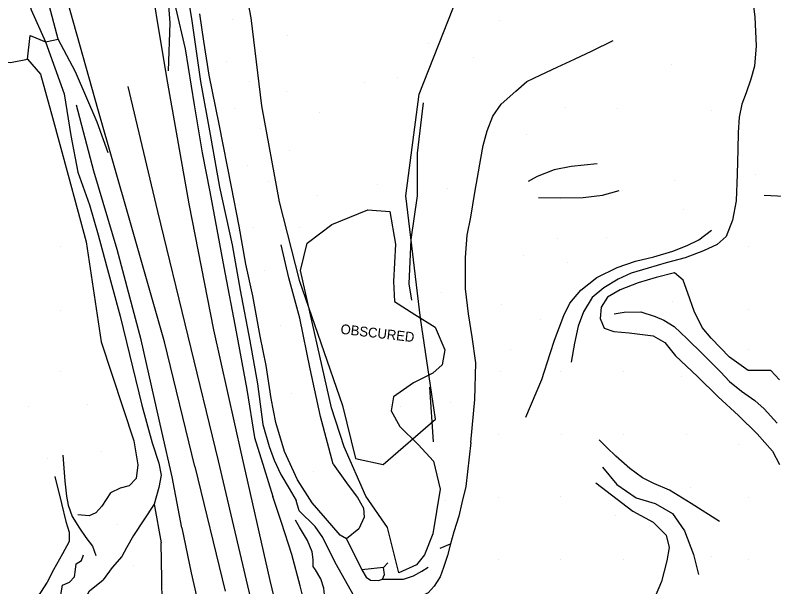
# Model space of a CAD drawing. Extents: x 524772 to 528246, y 273285 to 283088.
# Drawn here: x 526883.1 to 527001.3, y 277096 to 277185.1 of the extents above; entities that cross this region are included whole.
import ezdxf

# ---------------------------------------------------------------- set-up
doc = ezdxf.new("R2010")
doc.units = 0
for name, color, linetype in [('Exist DTM Crownline', 7, 'Continuous'), ('Exist Roads EOP', 7, 'Continuous'), ('Old_Level_12', 7, 'Continuous'), ('PH Exist DTM Breakline', 7, 'Continuous'), ('PH Exist DTM Obscure Area', 7, 'Continuous'), ('PH Exist DTM Obscure Area Text', 7, 'Continuous'), ('PH Exist DTM Point', 7, 'Continuous')]:
    doc.layers.add(name, color=color, linetype=linetype)

msp = doc.modelspace()

# ---------------------------------------------------------------- linework, layer by layer
at = {"layer": 'Exist DTM Crownline'}
for points in [[(526914.79, 277115.69), (526910.06, 277135.12), (526905.32, 277154.55), (526900.69, 277174)], [(526919.33, 277096.21), (526914.79, 277115.69)], [(526947.06, 276979.45), (526942.42, 276998.91), (526937.88, 277018.39), (526933.24, 277037.84), (526928.61, 277057.3), (526923.97, 277076.75), (526919.33, 277096.21)]]:
    msp.add_lwpolyline(points, dxfattribs=at)
at = {"layer": 'Exist Roads EOP'}
for points in [[(526900.85, 277153.48), (526896.06, 277170.16), (526889.3, 277194.22), (526884.63, 277212.43), (526879.92, 277231.7), (526876.48, 277244.99), (526874.79, 277251.63), (526873.56, 277255.42), (526872.21, 277259), (526870.14, 277262.76), (526866.56, 277267.72), (526863.21, 277269.57), (526861.12, 277271.45), (526858.18, 277272.32), (526855.9, 277272.51), (526842.82, 277270.02)], [(526918.39, 277116.54), (526914.05, 277136.07), (526910.19, 277155.71), (526906.72, 277175.44), (526903.44, 277195.22), (526899.97, 277214.95)], [(526911.1, 277114.8), (526906.36, 277134.24), (526900.85, 277153.48)], [(526922.83, 277097.04), (526918.39, 277116.54)], [(526911.1, 277114.8), (526915.83, 277095.37)], [(526950.66, 276980.31), (526946.02, 276999.77), (526941.38, 277019.22), (526936.75, 277038.68), (526932.11, 277058.13), (526927.47, 277077.59), (526922.83, 277097.04)]]:
    msp.add_lwpolyline(points, dxfattribs=at)
at = {"layer": 'Old_Level_12'}
msp.add_lwpolyline([(526918, 277194.33), (526919.81, 277184.72), (526921.45, 277171.02), (526924.24, 277156.03), (526927.35, 277143.85), (526934.11, 277124.3), (526936.12, 277116.04), (526940.41, 277115.08), (526948.6, 277122.14), (526946.23, 277137.9), (526943.97, 277156.98), (526946.05, 277172.83), (526953.62, 277192.1)], dxfattribs=at)
at = {"layer": 'PH Exist DTM Breakline'}
for points in [[(526897.58, 277163.67), (526895.87, 277168.46), (526892.48, 277176.3), (526889.8, 277181.4), (526886.36, 277194.4), (526883.53, 277204.48), (526881.07, 277212.38), (526878.38, 277221.11), (526875.84, 277229.51), (526876.25, 277230.28), (526876.28, 277232.3), (526876.33, 277233.77), (526876.07, 277235.6), (526875.05, 277239.42), (526873.73, 277244.72), (526872.03, 277251.84), (526869.74, 277261.27), (526868.77, 277263.43), (526868.32, 277264.16), (526867.85, 277264.89), (526867.37, 277265.6), (526866.86, 277266.3), (526866.33, 277266.98), (526865.86, 277267.56)], [(526906.97, 277176.46), (526907.26, 277183.92), (526906.54, 277192.83), (526905.68, 277202.3), (526904.42, 277210.29), (526901.93, 277222), (526900, 277232.75), (526897.48, 277243.97), (526894.73, 277254.19), (526893.28, 277259.49), (526891.98, 277264.64)], [(526855.06, 277212.76), (526856.34, 277212.18), (526857.4, 277211.26), (526858.14, 277210.06), (526858.93, 277206.93), (526859.52, 277203.5), (526860.43, 277200.78), (526861.96, 277196.97), (526864.54, 277192.44), (526867.83, 277188.37), (526869.48, 277186.49), (526870.82, 277184.15), (526871.02, 277181.99), (526870.94, 277180.29), (526874.53, 277179.12), (526877.73, 277178.28), (526879.55, 277178.02), (526882.35, 277177.75), (526884.99, 277178.27), (526885.43, 277181.95), (526887.82, 277180.97), (526889.8, 277181.4)], [(526906.54, 277192.83), (526909.56, 277179.91), (526910.98, 277171.16), (526912.24, 277163.7), (526913.41, 277157.58), (526915.6, 277145.86), (526917.52, 277135.8), (526919.17, 277126.79), (526920.37, 277119.33), (526921.89, 277114.46), (526923.25, 277110.11)], [(526908.99, 277193.83), (526910.57, 277184.61), (526911.99, 277174.8), (526913.47, 277166.55), (526914.92, 277158.33), (526916.92, 277149.34), (526918.16, 277142.26), (526919.64, 277134.38), (526920.84, 277127.67), (526921.7, 277121.31), (526922.66, 277117.88), (526923.44, 277115.79), (526924.47, 277113.54), (526925.77, 277111.36), (526926.86, 277109.48)], [(526884.2, 277190.95), (526885.6, 277185.94), (526887.82, 277180.97)], [(526997.58, 277190.73), (526998.34, 277184.84), (526998.53, 277180.37), (526998.28, 277177.18), (526997.7, 277175.17), (526996.95, 277173.03), (526996.32, 277171.28), (526995.87, 277169.24), (526995.74, 277166.87), (526995.67, 277164.21), (526995.55, 277160.34)], [(526929.34, 277109.11), (526927.06, 277112.73), (526925.03, 277117.13), (526923.68, 277121.63), (526922.98, 277125.37), (526922.18, 277130.51), (526921.26, 277135.1), (526920.11, 277141.41), (526919.05, 277146.33), (526917.98, 277152.25), (526916.79, 277158.39), (526914.86, 277168.16), (526913.29, 277175.77), (526912.51, 277181.06), (526911.86, 277185.35)], [(526887.82, 277180.97), (526890.74, 277172.87), (526891.75, 277166.4), (526892.88, 277160.67), (526894.65, 277155.57), (526896, 277150.89), (526897.3, 277146.05), (526899.46, 277138.22), (526902.82, 277124.35), (526904.43, 277118.49), (526905.5, 277115.29), (526905.83, 277113.45), (526905.47, 277111.52), (526904.73, 277108.91), (526905.82, 277102.91)], [(526954.06, 277118.51), (526954.7, 277125.23), (526954.84, 277130.97), (526954.3, 277135), (526953.7, 277138.58), (526953.23, 277142.46), (526953.26, 277147.35), (526953.53, 277150.85), (526954.09, 277153.65), (526954.72, 277157.5), (526955.12, 277159.82), (526955.65, 277162.8), (526955.98, 277164.8), (526956.61, 277167.08), (526957.5, 277169.37), (526958.82, 277171.26), (526961.07, 277173.28), (526962.79, 277174.77), (526964.99, 277175.81), (526967.52, 277177.02), (526970.22, 277178.27), (526973, 277179.57), (526976.27, 277181.2)], [(526884.99, 277178.27), (526887.06, 277175.96), (526888.92, 277169.18), (526891.37, 277160.21), (526894.14, 277149.81), (526896.48, 277134.23), (526901.56, 277118.78), (526902.18, 277115.06), (526901.95, 277112.94), (526900.86, 277111.8), (526899.46, 277111.39), (526897.93, 277110.69), (526896.59, 277108.58), (526895.66, 277107.56), (526894.6, 277107.08), (526892.87, 277107.23)], [(526909.07, 277105.24), (526907.57, 277113.2), (526905.95, 277120.23), (526902.72, 277134.53), (526899, 277148.6), (526895.37, 277160.84), (526892.65, 277171.11)], [(526946.64, 277171.48), (526945.71, 277163.6), (526945.71, 277156.99), (526944.75, 277150.16), (526944.4, 277143.28), (526944.82, 277140.71)], [(526973.76, 277161.95), (526969.69, 277161.57), (526967.06, 277161.03), (526964.43, 277159.99), (526963.01, 277159.21)], [(526995.55, 277160.34), (526995.4, 277156.21), (526994.86, 277153.18), (526993.84, 277150.62), (526992.44, 277149.37), (526990.33, 277148.41), (526987.45, 277147.31), (526984.49, 277146.52), (526981.7, 277145.71), (526979.05, 277144.91), (526977.01, 277143.97), (526974.79, 277142.65), (526972.99, 277141.12), (526971.63, 277138.92), (526970.79, 277136.64), (526970.25, 277134.03), (526969.71, 277131.06)], [(526964.64, 277156.69), (526968.09, 277156.64), (526971.6, 277156.7), (526974.61, 277157.1), (526977.17, 277157.79)], [(526999.77, 277157.08), (527009.19, 277156.6), (527015.1, 277156.36), (527021.36, 277156.52)], [(526962.66, 277122.48), (526965.13, 277128.33), (526966.45, 277132.4), (526967.14, 277134.49), (526968.56, 277138.33), (526969.51, 277140.24), (526971.21, 277142.26), (526973.73, 277144.25), (526976.87, 277145.82), (526979.74, 277146.8), (526982.6, 277147.49), (526985.54, 277148.36), (526987.76, 277149.21), (526989.61, 277150.12), (526991.58, 277151.61)], [(526932.63, 277115.13), (526930.64, 277122.58), (526929.03, 277130.01), (526927.43, 277137.89), (526925.72, 277144.21), (526924.52, 277149.33)], [(527002.19, 277128.29), (527000.82, 277129.74), (526999.6, 277129.76), (526997.3, 277129.73), (526994.38, 277131.82), (526991.52, 277134.78), (526990.13, 277136.44), (526988.87, 277139), (526987.91, 277141.78), (526987.16, 277143.84), (526985.81, 277144.95), (526982.97, 277144.25), (526980.15, 277143.41), (526977.36, 277142.31), (526975.37, 277141.16), (526974.39, 277139.64), (526974.21, 277137.87), (526974.83, 277136.34), (526976.34, 277135.81), (526978.75, 277135.6), (526982.51, 277135.14), (526984.29, 277134.12), (526985.97, 277132.02), (526989.38, 277128.8), (526992.62, 277125.67), (526995.76, 277122.74), (526998.68, 277119.87), (527001.09, 277117.18), (527002.18, 277115.11)], [(526976.42, 277138.56), (526977.99, 277138.83), (526980.57, 277138.89), (526982.8, 277138.16), (526984.16, 277137.6), (526985.78, 277136.63), (526987.72, 277134.75), (526990.2, 277132.28), (526992.97, 277129.53), (526994.39, 277128.03), (526996.25, 277126.53), (526998.35, 277125.1), (526999.77, 277123.8), (527001.81, 277121.56)], [(526947.64, 277127.14), (526948.22, 277118.64)], [(526954.06, 277118.51), (526953.28, 277111.66), (526952.69, 277109.11), (526952.21, 277107.03), (526951.45, 277104.61), (526950.92, 277102.76), (526950.43, 277100.9), (526949.81, 277099.06), (526949.3, 277097.61), (526948.35, 277096.12), (526947.41, 277095.08), (526945.41, 277094.07), (526943.63, 277093.23), (526941.91, 277092.75), (526940.03, 277092.59), (526938.84, 277092.64), (526937.45, 277093.03), (526935.98, 277094.48), (526932.93, 277099.84), (526931.02, 277103.72), (526929.81, 277105.42), (526927.33, 277107.9), (526926.86, 277109.48)], [(526992.82, 277106.2), (526988.42, 277109.03), (526985.03, 277111.1), (526982.61, 277112.15), (526980.81, 277113.04), (526978.85, 277114.47), (526976.69, 277116.38), (526975.27, 277117.75), (526974.05, 277118.95)], [(526890.51, 277116.54), (526890.85, 277112.5), (526891.09, 277110.18), (526891.35, 277108.74), (526891.98, 277107.01), (526893.12, 277105.18), (526894.1, 277103.72), (526895.14, 277102.37), (526895.64, 277100.93)], [(526932.63, 277115.13), (526934.99, 277111.89), (526936.43, 277109.95), (526937.36, 277108.28), (526937.44, 277106.89), (526936.65, 277105.09), (526934.7, 277103.49), (526933.72, 277104.11), (526931.46, 277106.76), (526929.34, 277109.11)], [(526974.58, 277114.7), (526976.83, 277112), (526979.86, 277109.9), (526982.82, 277109.01), (526985.49, 277107.46), (526987.39, 277104.74), (526988.75, 277101.09), (526989.56, 277097.96)], [(526889.26, 277113.23), (526890.29, 277109), (526890.99, 277106.23), (526891.49, 277104.54), (526891.49, 277103.11), (526890.46, 277101.19), (526889.09, 277098.66), (526888.08, 277096.75), (526887.04, 277095.15), (526885.78, 277093.39), (526884.68, 277091.74), (526883.35, 277090.16), (526879.82, 277087.61)], [(526973.53, 277112.25), (526979.34, 277107.83), (526982.48, 277106.11), (526984.5, 277104.08), (526985, 277102.17), (526984.64, 277100.11), (526983.76, 277096.88), (526982.82, 277094.53), (526981.08, 277091.66)], [(526944.46, 277022.3), (526939.61, 277043.03), (526937, 277054.06), (526933.31, 277070.43), (526931.01, 277081.5), (526928.33, 277092.86), (526927.5, 277096.2), (526926.22, 277101.05), (526924.56, 277106.04), (526923.25, 277110.11)], [(526904.73, 277108.91), (526901.54, 277104.05), (526900.46, 277102.09), (526899.7, 277100.75), (526898.2, 277099.03), (526896.81, 277097.13)], [(526951.29, 277030.18), (526947.91, 277043.77), (526945.04, 277053.33), (526942.87, 277060.17), (526935.07, 277084.69), (526931.36, 277094.26), (526931.16, 277095.83), (526930.69, 277097.27), (526929.87, 277098.7), (526929.52, 277099.22), (526929.5, 277100.29), (526929.34, 277101.48), (526928.62, 277103.24), (526927.38, 277105.34), (526926.77, 277106.4)], [(526909.07, 277105.24), (526910.51, 277098.23), (526911.78, 277092.77)], [(526934.7, 277103.49), (526937.12, 277098.66), (526937.76, 277097.52), (526938.45, 277097.09), (526939.7, 277097.04), (526940.31, 277097.23), (526940.64, 277097.98), (526940.49, 277099.06)], [(526908.98, 277043.29), (526908.38, 277045.99), (526908.18, 277048.67), (526908.1, 277052.59), (526908.19, 277057.88), (526907.55, 277067.01), (526907.54, 277072.42), (526907.06, 277078.61), (526906.46, 277085.52), (526905.96, 277090.66), (526905.99, 277093.61), (526905.93, 277097.25), (526905.82, 277102.91)], [(526949.28, 277102.06), (526950.92, 277102.76)], [(526881.72, 277080.59), (526884.59, 277083.87), (526886.36, 277086.86), (526888.18, 277090.22), (526889.38, 277092.8), (526890.21, 277094.81), (526890.47, 277096.27), (526891.56, 277096.74), (526892.35, 277097.61), (526892.47, 277098.72), (526892.59, 277099.6), (526893.41, 277100.15), (526893.72, 277101.04)], [(526940.49, 277099.06), (526941.13, 277099.78)], [(526940.49, 277099.06), (526937.12, 277098.66)], [(526940.31, 277097.23), (526943.61, 277097.21), (526945.16, 277097.75), (526946.44, 277098.48), (526947.43, 277099.12)], [(526885.74, 277078.6), (526887.88, 277081.28), (526889.95, 277084.79), (526891.49, 277088.43), (526892.67, 277091.25), (526893.64, 277093.52), (526894.65, 277095.41), (526896.81, 277097.13)]]:
    msp.add_lwpolyline(points, dxfattribs=at)
at = {"layer": 'PH Exist DTM Obscure Area'}
msp.add_lwpolyline([(526942.84, 277098.24), (526941.12, 277105.3), (526937.7, 277110.15), (526934.37, 277117.87), (526932.4, 277123.94), (526927.55, 277145.34), (526928.56, 277149.61), (526932.44, 277152.49), (526938.05, 277154.79), (526941.46, 277154.51), (526942.37, 277149.43), (526942.05, 277143.6), (526942.21, 277140.53), (526945.38, 277138.48), (526948.5, 277136.49), (526950.01, 277132.96), (526949.6, 277130.64), (526948.18, 277129.36), (526945.16, 277127.84), (526942.05, 277125.66), (526941.65, 277123.45), (526943.02, 277121.01), (526945.87, 277118.21), (526948.24, 277115.64), (526949.3, 277111.27), (526948.16, 277104.31), (526946.88, 277101.04), (526945.6, 277099.46), (526942.84, 277098.24)], dxfattribs=at)
at = {"layer": 'PH Exist DTM Point'}
for p, q in [((526916.99, 277184.48), (526916.99, 277184.48)), ((526958.47, 277184.24), (526958.47, 277184.24)), ((526925.46, 277182.02), (526925.46, 277182.02)), ((526947.42, 277180.66), (526947.42, 277180.66)), ((526916.02, 277177.97), (526916.02, 277177.97)), ((526954.5, 277178.5), (526954.5, 277178.5)), ((526985.32, 277177.51), (526985.32, 277177.51)), ((526942.73, 277175.35), (526942.73, 277175.35)), ((526919.63, 277174.78), (526919.63, 277174.78)), ((526937.44, 277174.7), (526937.44, 277174.7)), ((526925.33, 277173.18), (526925.33, 277173.18)), ((526917.32, 277170.51), (526917.32, 277170.51)), ((526968.87, 277170.72), (526968.87, 277170.72)), ((526976.98, 277170.52), (526976.98, 277170.52)), ((526930.49, 277169.93), (526930.49, 277169.93)), ((526991.55, 277170.23), (526991.55, 277170.23)), ((526921.39, 277167.52), (526921.39, 277167.52)), ((526962.72, 277166.51), (526962.72, 277166.51)), ((526925.79, 277164.09), (526925.79, 277164.09)), ((526919.29, 277161.76), (526919.29, 277161.76)), ((526998.37, 277160.3), (526998.37, 277160.3)), ((526922.52, 277159.28), (526922.52, 277159.28)), ((526939.61, 277158.78), (526939.61, 277158.78)), ((526985.79, 277159.39), (526985.79, 277159.39)), ((526950.38, 277158.12), (526950.38, 277158.12)), ((526930.12, 277156.98), (526930.12, 277156.98)), ((526987.24, 277154.84), (526987.24, 277154.84)), ((526920.24, 277152.07), (526920.24, 277152.07)), ((526927.41, 277152.05), (526927.41, 277152.05)), ((526967.65, 277150.25), (526967.65, 277150.25)), ((526975.19, 277150.55), (526975.19, 277150.55)), ((526890.09, 277149.03), (526890.09, 277149.03)), ((526997.38, 277149.03), (526997.38, 277149.03)), ((526962.33, 277147.61), (526962.33, 277147.61)), ((526969.15, 277146.66), (526969.15, 277146.66)), ((526922.01, 277145.36), (526922.01, 277145.36)), ((526949.5, 277141.93), (526949.5, 277141.93)), ((526958.91, 277140.1), (526958.91, 277140.1)), ((526985.5, 277140.43), (526985.5, 277140.43)), ((526890.19, 277139.14), (526890.19, 277139.14)), ((526997.38, 277139.28), (526997.38, 277139.28)), ((526964.92, 277137.64), (526964.92, 277137.64)), ((526924.36, 277136.81), (526924.36, 277136.81)), ((526960.29, 277133.04), (526960.29, 277133.04)), ((526997.4, 277132.97), (526997.4, 277132.97)), ((526890.09, 277129.53), (526890.09, 277129.53)), ((526958.71, 277129.55), (526958.71, 277129.55)), ((526968.11, 277129.53), (526968.11, 277129.53)), ((526977.87, 277129.53), (526977.87, 277129.53)), ((526986.95, 277128.85), (526986.95, 277128.85)), ((526926.15, 277126.11), (526926.15, 277126.11)), ((526894.36, 277124.43), (526894.36, 277124.43)), ((526950.93, 277124.8), (526950.93, 277124.8)), ((526885.1, 277124.14), (526885.1, 277124.14)), ((526943.16, 277124.17), (526943.16, 277124.17)), ((526958.36, 277119.77), (526958.36, 277119.77)), ((526968.13, 277119.8), (526968.13, 277119.8)), ((526977.86, 277119.75), (526977.86, 277119.75)), ((526987.62, 277119.77), (526987.62, 277119.77)), ((526995.76, 277118.17), (526995.76, 277118.17)), ((526888.19, 277116.05), (526888.19, 277116.05)), ((526896.49, 277117.1), (526896.49, 277117.1)), ((526929.51, 277114.06), (526929.51, 277114.06)), ((526988.3, 277111.58), (526988.3, 277111.58)), ((526968.1, 277110.05), (526968.1, 277110.05)), ((526950.15, 277109.5), (526950.15, 277109.5)), ((526958.36, 277110.02), (526958.36, 277110.02)), ((526997.38, 277110.02), (526997.38, 277110.02)), ((526976.69, 277107.14), (526976.69, 277107.14)), ((526898.97, 277105.74), (526898.97, 277105.74)), ((526991.61, 277100.79), (526991.61, 277100.79)), ((526901.5, 277099.43), (526901.5, 277099.43)), ((526958.36, 277100.26), (526958.36, 277100.26)), ((526968.11, 277100.26), (526968.11, 277100.26)), ((526977.87, 277100.26), (526977.87, 277100.26)), ((526997.38, 277100.26), (526997.38, 277100.26))]:
    msp.add_line(p, q, dxfattribs=at)

# ---------------------------------------------------------------- texts
at = {"layer": 'PH Exist DTM Obscure Area Text'}
msp.add_text('OBSCURED', height=1.524, rotation=353.4693, dxfattribs=at).set_placement((526933.72, 277135.48))

doc.saveas('drawing.dxf')
